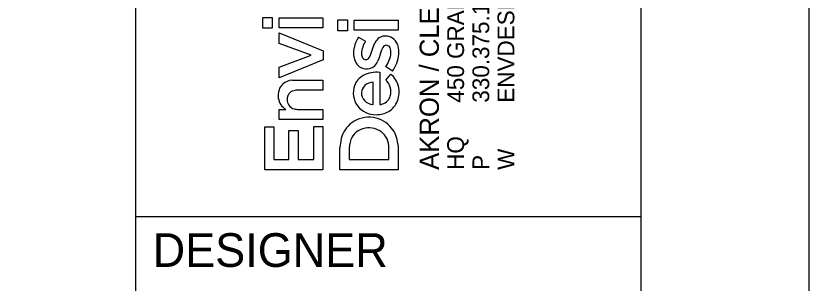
# Model space of a CAD drawing. Extents: x -0.4 to 34, y 0 to 22.
# Drawn here: x 31.644 to 34, y 2.302 to 3.095 of the extents above; entities that cross this region are included whole.
import ezdxf

# ---------------------------------------------------------------- set-up
doc = ezdxf.new("R2010")
doc.units = 0
for name, color, linetype in [('DR_P_Erosion_Control', 7, 'Continuous'), ('DR_P_Headwall', 7, 'Continuous'), ('GK_Drainage_Nodes', 7, 'Continuous')]:
    doc.layers.add(name, color=color, linetype=linetype)

msp = doc.modelspace()

# ---------------------------------------------------------------- linework, layer by layer
at = {"layer": 'DR_P_Erosion_Control'}
for p, q in [((32, 0.5), (32, 21.5)), ((32, 2.5), (33.5, 2.5))]:
    msp.add_line(p, q, dxfattribs=at)
msp.add_lwpolyline([(1.5, 21.5), (33.5, 21.5), (33.5, 0.5), (1.5, 0.5)], close=True, dxfattribs=at)
at = {"layer": 'DR_P_Headwall'}
msp.add_lwpolyline([(0, 0), (34, 0), (34, 22), (0, 22)], close=True, dxfattribs=at)
at = {"layer": 'GK_Drainage_Nodes'}
for p, q in [((32.3771, 3.0582), (32.3771, 3.0903)), ((32.3771, 3.0903), (32.4054, 3.0903)), ((32.4054, 3.0903), (32.4054, 3.0582)), ((32.4254, 3.0594), (32.4254, 3.0893)), ((32.4254, 3.0893), (32.5557, 3.0893)), ((32.5557, 3.0893), (32.5557, 3.0594)), ((32.6005, 3.0511), (32.6005, 3.0832)), ((32.6005, 3.0832), (32.6289, 3.0832)), ((32.6289, 3.0832), (32.6289, 3.0511)), ((32.6489, 3.0523), (32.6489, 3.0822)), ((32.6489, 3.0822), (32.7792, 3.0822)), ((32.7792, 3.0822), (32.7792, 3.0523)), ((32.4054, 3.0582), (32.3771, 3.0582)), ((32.5557, 3.0594), (32.4254, 3.0594)), ((32.4254, 3.0133), (32.4254, 3.0446)), ((32.4254, 3.0446), (32.5567, 2.9913)), ((32.6289, 3.0511), (32.6005, 3.0511)), ((32.7792, 3.0523), (32.6489, 3.0523)), ((32.6615, 3.0321), (32.6827, 3.0203)), ((32.5212, 2.978), (32.4254, 3.0133)), ((32.6967, 2.9787), (32.7048, 3.0026)), ((32.7048, 3.0026), (32.7104, 3.0153)), ((32.7298, 2.9933), (32.7221, 2.9688)), ((32.7334, 3.001), (32.7298, 2.9933)), ((32.4254, 2.9429), (32.5212, 2.978)), ((32.5567, 2.9913), (32.5567, 2.9644)), ((32.693, 2.9712), (32.6967, 2.9787)), ((32.5567, 2.9644), (32.4254, 2.9109)), ((32.7221, 2.9688), (32.7182, 2.9592)), ((32.4254, 2.9109), (32.4254, 2.9429)), ((32.7245, 2.9275), (32.7246, 2.8319)), ((32.7621, 2.9314), (32.742, 2.9447)), ((32.7423, 2.9046), (32.7577, 2.922)), ((32.4644, 2.904), (32.4729, 2.9044)), ((32.4729, 2.9044), (32.5557, 2.9044)), ((32.5557, 2.9044), (32.5557, 2.8746)), ((32.7049, 2.8318), (32.7049, 2.8983)), ((32.5557, 2.8746), (32.4814, 2.8746)), ((32.7036, 2.8317), (32.7049, 2.8318)), ((32.4254, 2.7875), (32.4254, 2.8173)), ((32.4254, 2.8173), (32.4455, 2.8173)), ((32.4822, 2.8173), (32.5557, 2.8173)), ((32.5557, 2.8173), (32.5557, 2.7876)), ((32.5557, 2.7876), (32.4254, 2.7875)), ((32.383, 2.6379), (32.383, 2.766)), ((32.383, 2.766), (32.4101, 2.766)), ((32.4101, 2.766), (32.4101, 2.6683)), ((32.5286, 2.6683), (32.5286, 2.7672)), ((32.5286, 2.7672), (32.5557, 2.7672)), ((32.5557, 2.7672), (32.5557, 2.6379)), ((32.455, 2.6683), (32.455, 2.7549)), ((32.455, 2.7549), (32.4822, 2.7549)), ((32.4822, 2.7549), (32.4822, 2.6683)), ((32.6347, 2.7118), (32.6341, 2.7023)), ((32.7785, 2.715), (32.7792, 2.7021)), ((32.6064, 2.638), (32.6064, 2.704)), ((32.6341, 2.7023), (32.6341, 2.6684)), ((32.7515, 2.6683), (32.7515, 2.7024)), ((32.7792, 2.7021), (32.7792, 2.638)), ((32.4101, 2.6683), (32.455, 2.6683)), ((32.4822, 2.6683), (32.5286, 2.6683)), ((32.6341, 2.6684), (32.7515, 2.6683)), ((32.5557, 2.6379), (32.383, 2.6379)), ((32.7792, 2.638), (32.6064, 2.638))]:
    msp.add_line(p, q, dxfattribs=at)
for points in [[(32.3771, 3.0582), (32.3771, 3.0903), (32.4054, 3.0903), (32.4054, 3.0582)], [(32.4254, 3.0594), (32.4254, 3.0893), (32.5557, 3.0893), (32.5557, 3.0594)], [(32.6005, 3.0511), (32.6005, 3.0832), (32.6289, 3.0832), (32.6289, 3.0511)], [(32.6489, 3.0523), (32.6489, 3.0822), (32.7792, 3.0822), (32.7792, 3.0523)], [(32.4254, 2.9109), (32.4254, 2.9429), (32.5212, 2.978), (32.4254, 3.0133), (32.4254, 3.0446), (32.5567, 2.9913), (32.5567, 2.9644)], [(32.383, 2.6379), (32.383, 2.766), (32.4101, 2.766), (32.4101, 2.6683), (32.455, 2.6683), (32.455, 2.7549), (32.4822, 2.7549), (32.4822, 2.6683), (32.5286, 2.6683), (32.5286, 2.7672), (32.5557, 2.7672), (32.5557, 2.6379)]]:
    msp.add_lwpolyline(points, close=True, dxfattribs=at)
for points in [[(32.6615, 3.0321), (32.6827, 3.0203)], [(32.693, 2.9712), (32.6967, 2.9787), (32.7048, 3.0026), (32.7104, 3.0153)], [(32.7334, 3.001), (32.7298, 2.9933), (32.7221, 2.9688), (32.7182, 2.9592)], [(32.7245, 2.9275), (32.7246, 2.8319)], [(32.7621, 2.9314), (32.742, 2.9447)], [(32.7423, 2.9046), (32.7577, 2.922)], [(32.4644, 2.904), (32.4729, 2.9044), (32.5557, 2.9044), (32.5557, 2.8746), (32.4814, 2.8746)], [(32.7036, 2.8317), (32.7049, 2.8318), (32.7049, 2.8983)], [(32.4254, 2.7875), (32.4254, 2.8173), (32.4455, 2.8173)], [(32.4822, 2.8173), (32.5557, 2.8173), (32.5557, 2.7876), (32.4254, 2.7875)], [(32.7785, 2.715), (32.7792, 2.7021), (32.7792, 2.638), (32.6064, 2.638)], [(32.6347, 2.7118), (32.6341, 2.7023), (32.6341, 2.6684), (32.7515, 2.6683), (32.7515, 2.7024)], [(32.6064, 2.638), (32.6064, 2.704)]]:
    msp.add_lwpolyline(points, dxfattribs=at)
for centre, radius, start, end in [((32.7364, 2.9826), 0.0897, 146.531, 178.7571), ((32.7364, 2.9826), 0.0897, 146.531, 178.7571), ((32.7452, 2.9789), 0.0749, 146.5112, 176.9101), ((32.7452, 2.9789), 0.0749, 146.5112, 176.9101), ((32.7466, 2.9971), 0.0405, 125.5118, 153.4159), ((32.7466, 2.9971), 0.0405, 125.5118, 153.4159), ((32.7406, 3.0026), 0.0326, 80.1719, 122.5197), ((32.7406, 3.0026), 0.0326, 80.1719, 122.5197), ((32.7428, 2.9982), 0.0367, 47.7934, 84.6892), ((32.7428, 2.9982), 0.0367, 47.7934, 84.6892), ((32.7379, 2.9946), 0.0427, 14.9966, 46.2063), ((32.7379, 2.9946), 0.0427, 14.9966, 46.2063), ((32.7438, 2.9963), 0.0114, 76.6609, 155.7053), ((32.7438, 2.9963), 0.0114, 76.6609, 155.7053), ((32.744, 2.9951), 0.0126, 21.5098, 78.5262), ((32.744, 2.9951), 0.0126, 21.5098, 78.5262), ((32.7259, 2.9877), 0.0321, 354.5726, 22.068), ((32.7259, 2.9877), 0.0321, 354.5726, 22.068), ((32.7104, 2.9867), 0.0712, 355.8306, 15.3914), ((32.7104, 2.9867), 0.0712, 355.8306, 15.3914), ((32.6967, 2.9824), 0.0501, 177.5366, 222.7932), ((32.6967, 2.9824), 0.0501, 177.5366, 222.7932), ((32.6931, 2.9823), 0.0228, 178.4747, 211.0868), ((32.6931, 2.9823), 0.0228, 178.4747, 211.0868), ((32.6833, 2.9767), 0.0115, 212.2368, 268.3777), ((32.6833, 2.9767), 0.0115, 212.2368, 268.3777), ((32.6834, 2.9759), 0.0107, 267.716, 333.7337), ((32.6834, 2.9759), 0.0107, 267.716, 333.7337), ((32.6825, 2.9915), 0.0757, 321.811, 354.7969), ((32.6825, 2.9915), 0.0757, 321.811, 354.7969), ((32.6895, 2.9882), 0.0922, 321.9777, 355.8738), ((32.6895, 2.9882), 0.0922, 321.9777, 355.8738), ((32.686, 2.9753), 0.0375, 225.9854, 302.4797), ((32.686, 2.9753), 0.0375, 225.9854, 302.4797), ((32.681, 2.9758), 0.0408, 308.0877, 335.9874), ((32.681, 2.9758), 0.0408, 308.0877, 335.9874), ((32.7152, 2.8441), 0.0838, 83.615, 118.2876), ((32.7152, 2.8441), 0.0838, 83.615, 118.2876), ((32.7174, 2.8717), 0.0644, 13.5336, 51.3615), ((32.7174, 2.8717), 0.0644, 13.5336, 51.3615), ((32.4687, 2.8543), 0.0499, 94.9696, 130.2225), ((32.4687, 2.8543), 0.0499, 94.9696, 130.2225), ((32.7024, 2.8691), 0.0558, 118.8308, 160.6244), ((32.7024, 2.8691), 0.0558, 118.8308, 160.6244), ((32.7079, 2.8561), 0.0424, 94.008, 130.8817), ((32.7079, 2.8561), 0.0424, 94.008, 130.8817), ((32.7038, 2.8656), 0.0549, 19.0357, 45.4406), ((32.7038, 2.8656), 0.0549, 19.0357, 45.4406), ((32.4787, 2.8582), 0.056, 162.2736, 187.7919), ((32.4787, 2.8582), 0.056, 162.2736, 187.7919), ((32.4635, 2.8626), 0.0402, 132.2219, 161.6818), ((32.4635, 2.8626), 0.0402, 132.2219, 161.6818), ((32.7104, 2.8661), 0.0644, 160.5201, 215.7831), ((32.7104, 2.8661), 0.0644, 160.5201, 215.7831), ((32.7005, 2.8663), 0.0298, 132.9851, 177.179), ((32.7005, 2.8663), 0.0298, 132.9851, 177.179), ((32.7107, 2.8697), 0.047, 344.6059, 17.007), ((32.7107, 2.8697), 0.047, 344.6059, 17.007), ((32.7064, 2.8692), 0.0758, 339.3542, 13.3785), ((32.7064, 2.8692), 0.0758, 339.3542, 13.3785), ((32.4748, 2.8487), 0.025, 103.6865, 182.2187), ((32.4748, 2.8487), 0.025, 103.6865, 182.2187), ((32.4811, 2.8286), 0.046, 89.6049, 105.3284), ((32.4811, 2.8286), 0.046, 89.6049, 105.3284), ((32.7017, 2.865), 0.0311, 175.0013, 223.283), ((32.7017, 2.865), 0.0311, 175.0013, 223.283), ((32.7224, 2.8671), 0.035, 288.0077, 343.5508), ((32.7224, 2.8671), 0.035, 288.0077, 343.5508), ((32.4703, 2.858), 0.0476, 188.962, 238.7037), ((32.4703, 2.858), 0.0476, 188.962, 238.7037), ((32.4773, 2.8456), 0.0276, 175.5854, 255.1439), ((32.4773, 2.8456), 0.0276, 175.5854, 255.1439), ((32.7125, 2.8705), 0.0687, 217.7452, 271.6543), ((32.7125, 2.8705), 0.0687, 217.7452, 271.6543), ((32.7089, 2.8736), 0.0423, 225.0619, 262.7974), ((32.7089, 2.8736), 0.0423, 225.0619, 262.7974), ((32.7247, 2.8522), 0.0202, 269.7003, 294.8711), ((32.7247, 2.8522), 0.0202, 269.7003, 294.8711), ((32.7189, 2.8652), 0.0626, 300.9427, 338.7323), ((32.7189, 2.8652), 0.0626, 300.9427, 338.7323), ((32.4818, 2.8595), 0.0422, 254.0916, 270.5284), ((32.4818, 2.8595), 0.0422, 254.0916, 270.5284), ((32.7155, 2.8724), 0.0706, 269.2048, 300.3341), ((32.7155, 2.8724), 0.0706, 269.2048, 300.3341), ((32.6923, 2.7079), 0.0864, 81.194, 125.9984), ((32.6923, 2.7079), 0.0864, 81.194, 125.9984), ((32.6946, 2.7113), 0.0827, 37.8521, 82.402), ((32.6946, 2.7113), 0.0827, 37.8521, 82.402), ((32.6939, 2.7089), 0.0865, 127.2362, 165.148), ((32.6939, 2.7089), 0.0865, 127.2362, 165.148), ((32.6889, 2.7078), 0.054, 106.1881, 157.3861), ((32.6889, 2.7078), 0.054, 106.1881, 157.3861), ((32.6928, 2.6986), 0.0639, 55.6727, 107.2093), ((32.6928, 2.6986), 0.0639, 55.6727, 107.2093), ((32.6859, 2.7057), 0.0931, 5.7333, 37.304), ((32.6859, 2.7057), 0.0931, 5.7333, 37.304), ((32.6929, 2.705), 0.0587, 357.4662, 52.2665), ((32.6929, 2.705), 0.0587, 357.4662, 52.2665), ((32.7143, 2.7028), 0.1078, 164.7861, 179.3704), ((32.7143, 2.7028), 0.1078, 164.7861, 179.3704), ((32.6983, 2.7039), 0.0641, 157.3571, 172.9275), ((32.6983, 2.7039), 0.0641, 157.3571, 172.9275)]:
    msp.add_arc(centre, radius, start, end, dxfattribs=at)

# ---------------------------------------------------------------- texts
for s, height, p in [('450 GRANT ST., AKRON, OH  44311', 0.049846, (32.9749, 2.8374)), ('AKRON / CLEVELAND / COLUMBUS', 0.056969, (32.9001, 2.638)), ('ENVDESIGNGROUP.COM', 0.049846, (33.1244, 2.8374)), ('330.375.1390', 0.049846, (33.0497, 2.8374)), ('HQ ', 0.04985, (32.9749, 2.638)), ('W', 0.0498, (33.1244, 2.638)), ('P', 0.0498, (33.0497, 2.638))]:
    msp.add_text(s, height=height, rotation=90, dxfattribs=at).set_placement(p)
msp.add_text('DESIGNER', height=0.1, dxfattribs=at).set_placement((32.05, 2.35))

doc.saveas('drawing.dxf')
